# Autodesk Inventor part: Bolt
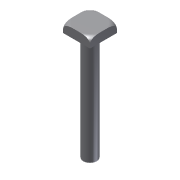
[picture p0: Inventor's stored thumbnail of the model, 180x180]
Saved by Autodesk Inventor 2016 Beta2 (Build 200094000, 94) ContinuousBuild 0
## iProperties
Created: 2009-04
Part Number: Bolt
Document SubType Name: Modeling
Designer: Sham
Density: 1 g/cm^3
Material: Generic
Appearance: Default
Author: Sham
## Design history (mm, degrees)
sketch "Sketch1"
  geometry: L1 (-12, 12)-(12, 12); L2 (12, 12)-(12, -12); L3 (12, -12)-(-12, -12); L4 (-12, -12)-(-12, 12); 1 further point
  constraints: 8 end point, 2 parallel, 2 perpendicular, 1 horizontal, 1 other
  dimensions: "d0" = 24 distance of L1.start L1.end; "d1" = 12 distance from line of L2 point (0, 0); "d2" = 12 distance from line of L1 point (0, 0)
extrude "Extrusion1" new body sketch "Sketch1" distance "d3" = 8; taper "d4" = 0 deg
sketch "Sketch2"
  geometry: C1 r 6 at (0, 0)
  constraints: 1 centre point
  dimensions: "d5" = 12 diameter of C1
extrude "Extrusion2" join sketch "Sketch2" distance "d6" = 96; taper "d7" = 0 deg
workpoint "Work Point1"
workplane "Work Plane1"
sketch "Sketch3"
  geometry: L1 (33.941, 5)-(33.941, 6); L2 (28.941, 0)-(28.405, 0); L3 (16.971, 125.007)-(16.971, -22.043) reference; A1 r 5 centre (28.941, 5) between (28.941, 0) and (33.941, 5); 1 further point
  constraints: 4 end point, 2 point on circle, 2 point on line, 2 tangent, 1 centre point, 1 perpendicular
  dimensions: "d10" = 5 radius of A1
revolve "Revolution1" sketch "Sketch3" stored, may be unused: angle "d12" = 90 deg
body "Solid1"
other parameters: "d11" = 90 deg
